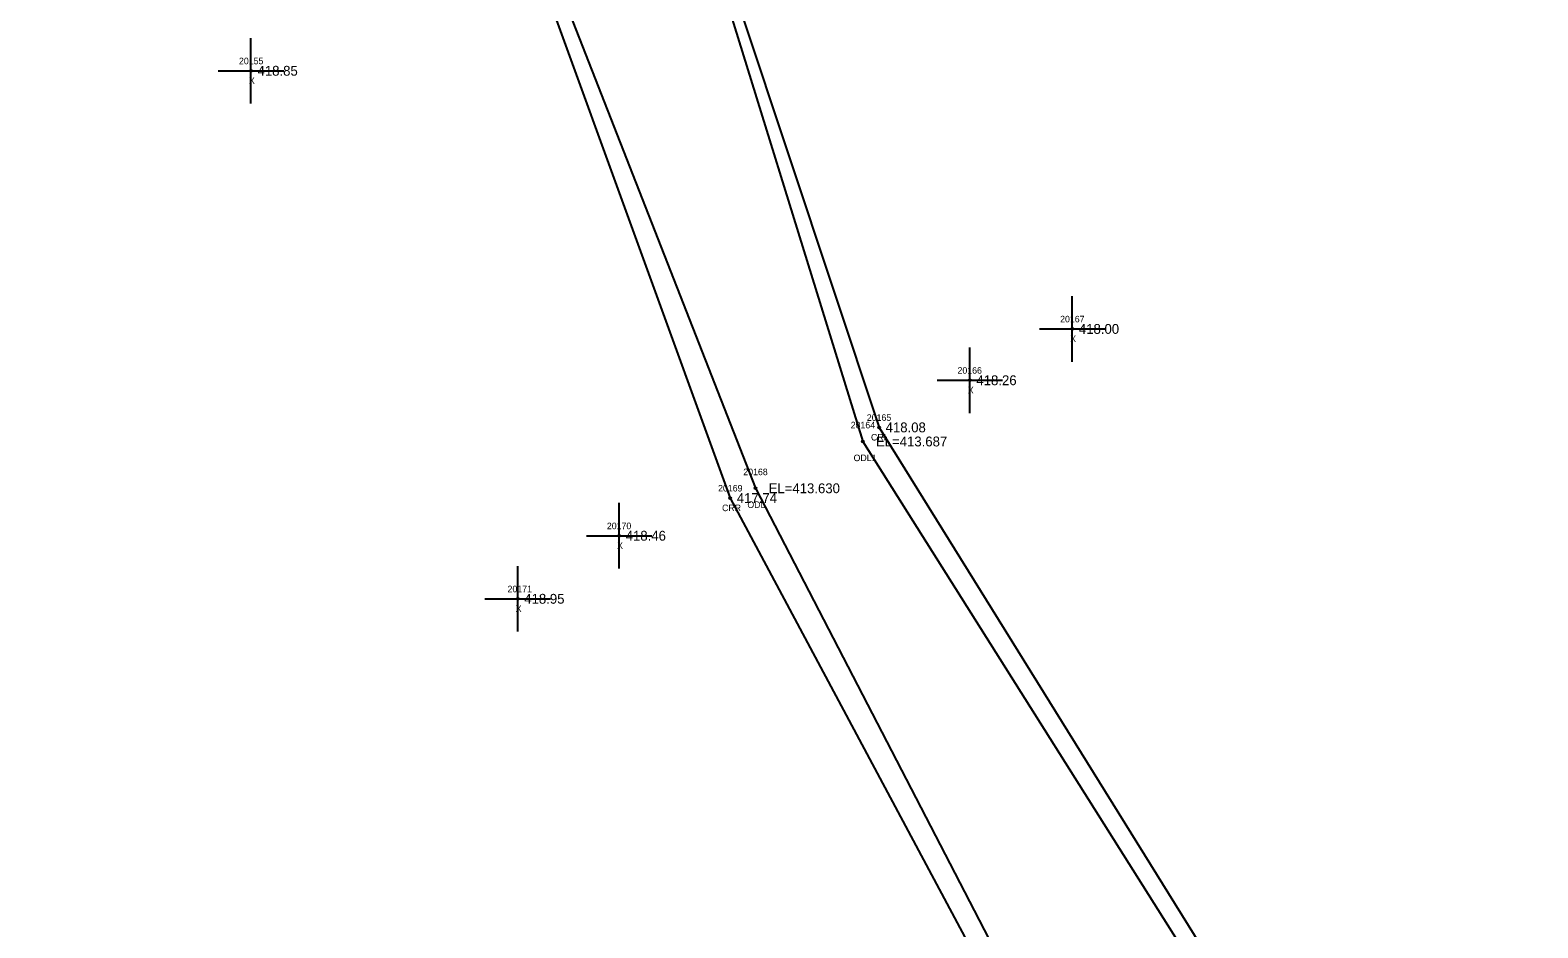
# Model space of a CAD drawing. Extents: x 1613184 to 1614731, y 770859 to 771868.
# Drawn here: x 1613909.3 to 1614139.2, y 770995.6 to 771132.5 of the extents above; entities that cross this region are included whole.
import ezdxf

# ---------------------------------------------------------------- set-up
doc = ezdxf.new("R2010")
doc.units = 0
for name, color, linetype in [('RD_EX_H2O', 7, 'Continuous'), ('RD_EX_H2O_txCode', 7, 'Continuous'), ('RD_EX_Misc', 7, 'Continuous'), ('RD_EX_Misc_txCode', 7, 'Continuous'), ('RD_EX_TX_H2O_ELEV', 7, 'Continuous'), ('RD_EX_TX_Misc_ELEV', 7, 'Continuous'), ('RD_SMD_Locator', 7, 'Continuous')]:
    doc.layers.add(name, color=color, linetype=linetype)

msp = doc.modelspace()

# ---------------------------------------------------------------- linework, layer by layer
at = {"layer": 'RD_EX_H2O'}
for points in [[(1613914.71, 771327.05), (1613912.94, 771270.2), (1613909.29, 771229.14), (1613936.32, 771173.24), (1613961.59, 771155.78), (1613976.99, 771153.11), (1613987.89, 771138.66), (1614016.07, 771061.15), (1614064.07, 770971.34), (1614114.62, 770881.02)], [(1613918.3, 771327.47), (1613915.56, 771269.65), (1613912.54, 771229.9), (1613937.35, 771175.56), (1613962.55, 771156.92), (1613978.15, 771155.33), (1613989.65, 771139.95), (1614019.92, 771062.64), (1614066.64, 770972.38), (1614116.22, 770882.03)], [(1613939.34, 771325.64), (1613936.19, 771267.33), (1613931.54, 771235.48), (1613951.01, 771188.77), (1613971.87, 771179.88), (1613985.53, 771176.18), (1614010.21, 771154.12), (1614036.29, 771069.78), (1614094.78, 770976.9), (1614137.18, 770892.4)], [(1613940.63, 771325.49), (1613938.42, 771267.33), (1613934.3, 771235.92), (1613956.7, 771194.52), (1613973.34, 771185.91), (1613987.6, 771179.19), (1614011.07, 771155.33), (1614038.76, 771071.93), (1614097.41, 770977.46), (1614139.24, 770893.98)]]:
    msp.add_lwpolyline(points, dxfattribs=at)
at = {"layer": 'RD_EX_Misc'}
for p, q in [((1613942.97, 771121.33), (1613942.97, 771131.33)), ((1613937.97, 771126.33), (1613947.97, 771126.33)), ((1614068.24, 771081.95), (1614068.24, 771091.95)), ((1614063.24, 771086.95), (1614073.24, 771086.95)), ((1614052.61, 771074.12), (1614052.61, 771084.12)), ((1614047.61, 771079.12), (1614057.61, 771079.12)), ((1613999.12, 771050.4), (1613999.12, 771060.4)), ((1613994.12, 771055.4), (1614004.12, 771055.4)), ((1613983.65, 771040.78), (1613983.65, 771050.78)), ((1613978.65, 771045.78), (1613988.65, 771045.78))]:
    msp.add_line(p, q, dxfattribs=at)
at = {"layer": 'RD_SMD_Locator'}
for centre in [(1613942.97, 771126.33), (1614068.24, 771086.95), (1614052.61, 771079.12), (1614038.76, 771071.93), (1614036.29, 771069.78), (1614016.07, 771061.15), (1614019.92, 771062.64), (1613999.12, 771055.4), (1613983.65, 771045.78)]:
    msp.add_circle(centre, 0.15, dxfattribs=at)

# ---------------------------------------------------------------- texts
at = {"layer": 'RD_EX_H2O_txCode'}
for s, p in [('20164', (1614034.44, 771071.78)), ('20165', (1614036.9, 771072.93)), ('CRL', (1614037.53, 771069.93)), ('ODL1', (1614034.88, 771066.78)), ('20168', (1614018.06, 771064.64)), ('20169', (1614014.21, 771062.15)), ('CRR', (1614014.82, 771059.15)), ('ODL', (1614018.68, 771059.64))]:
    msp.add_text(s, height=1, dxfattribs=at).set_placement(p)
at = {"layer": 'RD_EX_Misc_txCode'}
for s, p in [('20155', (1613941.14, 771127.33)), ('X', (1613942.66, 771124.33)), ('20167', (1614066.38, 771087.95)), ('X', (1614067.92, 771084.95)), ('20166', (1614050.73, 771080.12)), ('X', (1614052.3, 771077.12)), ('20170', (1613997.25, 771056.4)), ('X', (1613998.81, 771053.4)), ('20171', (1613982.1, 771046.78)), ('X', (1613983.34, 771043.78))]:
    msp.add_text(s, height=1, dxfattribs=at).set_placement(p)
at = {"layer": 'RD_EX_TX_H2O_ELEV'}
for s, p in [('EL=413.687', (1614038.29, 771069.03)), ('418.08', (1614039.76, 771071.18)), ('417.74', (1614017.07, 771060.4)), ('EL=413.630', (1614021.92, 771061.89))]:
    msp.add_text(s, height=1.5, dxfattribs=at).set_placement(p)
at = {"layer": 'RD_EX_TX_Misc_ELEV'}
for s, p in [('418.85', (1613943.97, 771125.58)), ('418.00', (1614069.24, 771086.2)), ('418.26', (1614053.61, 771078.37)), ('418.46', (1614000.12, 771054.65)), ('418.95', (1613984.65, 771045.03))]:
    msp.add_text(s, height=1.5, dxfattribs=at).set_placement(p)

doc.saveas('drawing.dxf')
